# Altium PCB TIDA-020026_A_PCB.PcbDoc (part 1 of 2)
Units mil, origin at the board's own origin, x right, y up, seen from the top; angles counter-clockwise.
Board outline 2952.76 x 2952.76 mil, 2 copper layers (Top Layer, Bottom Layer), stack 62 mil thick; 75 components, 57 nets, 258 pads, 285 vias.
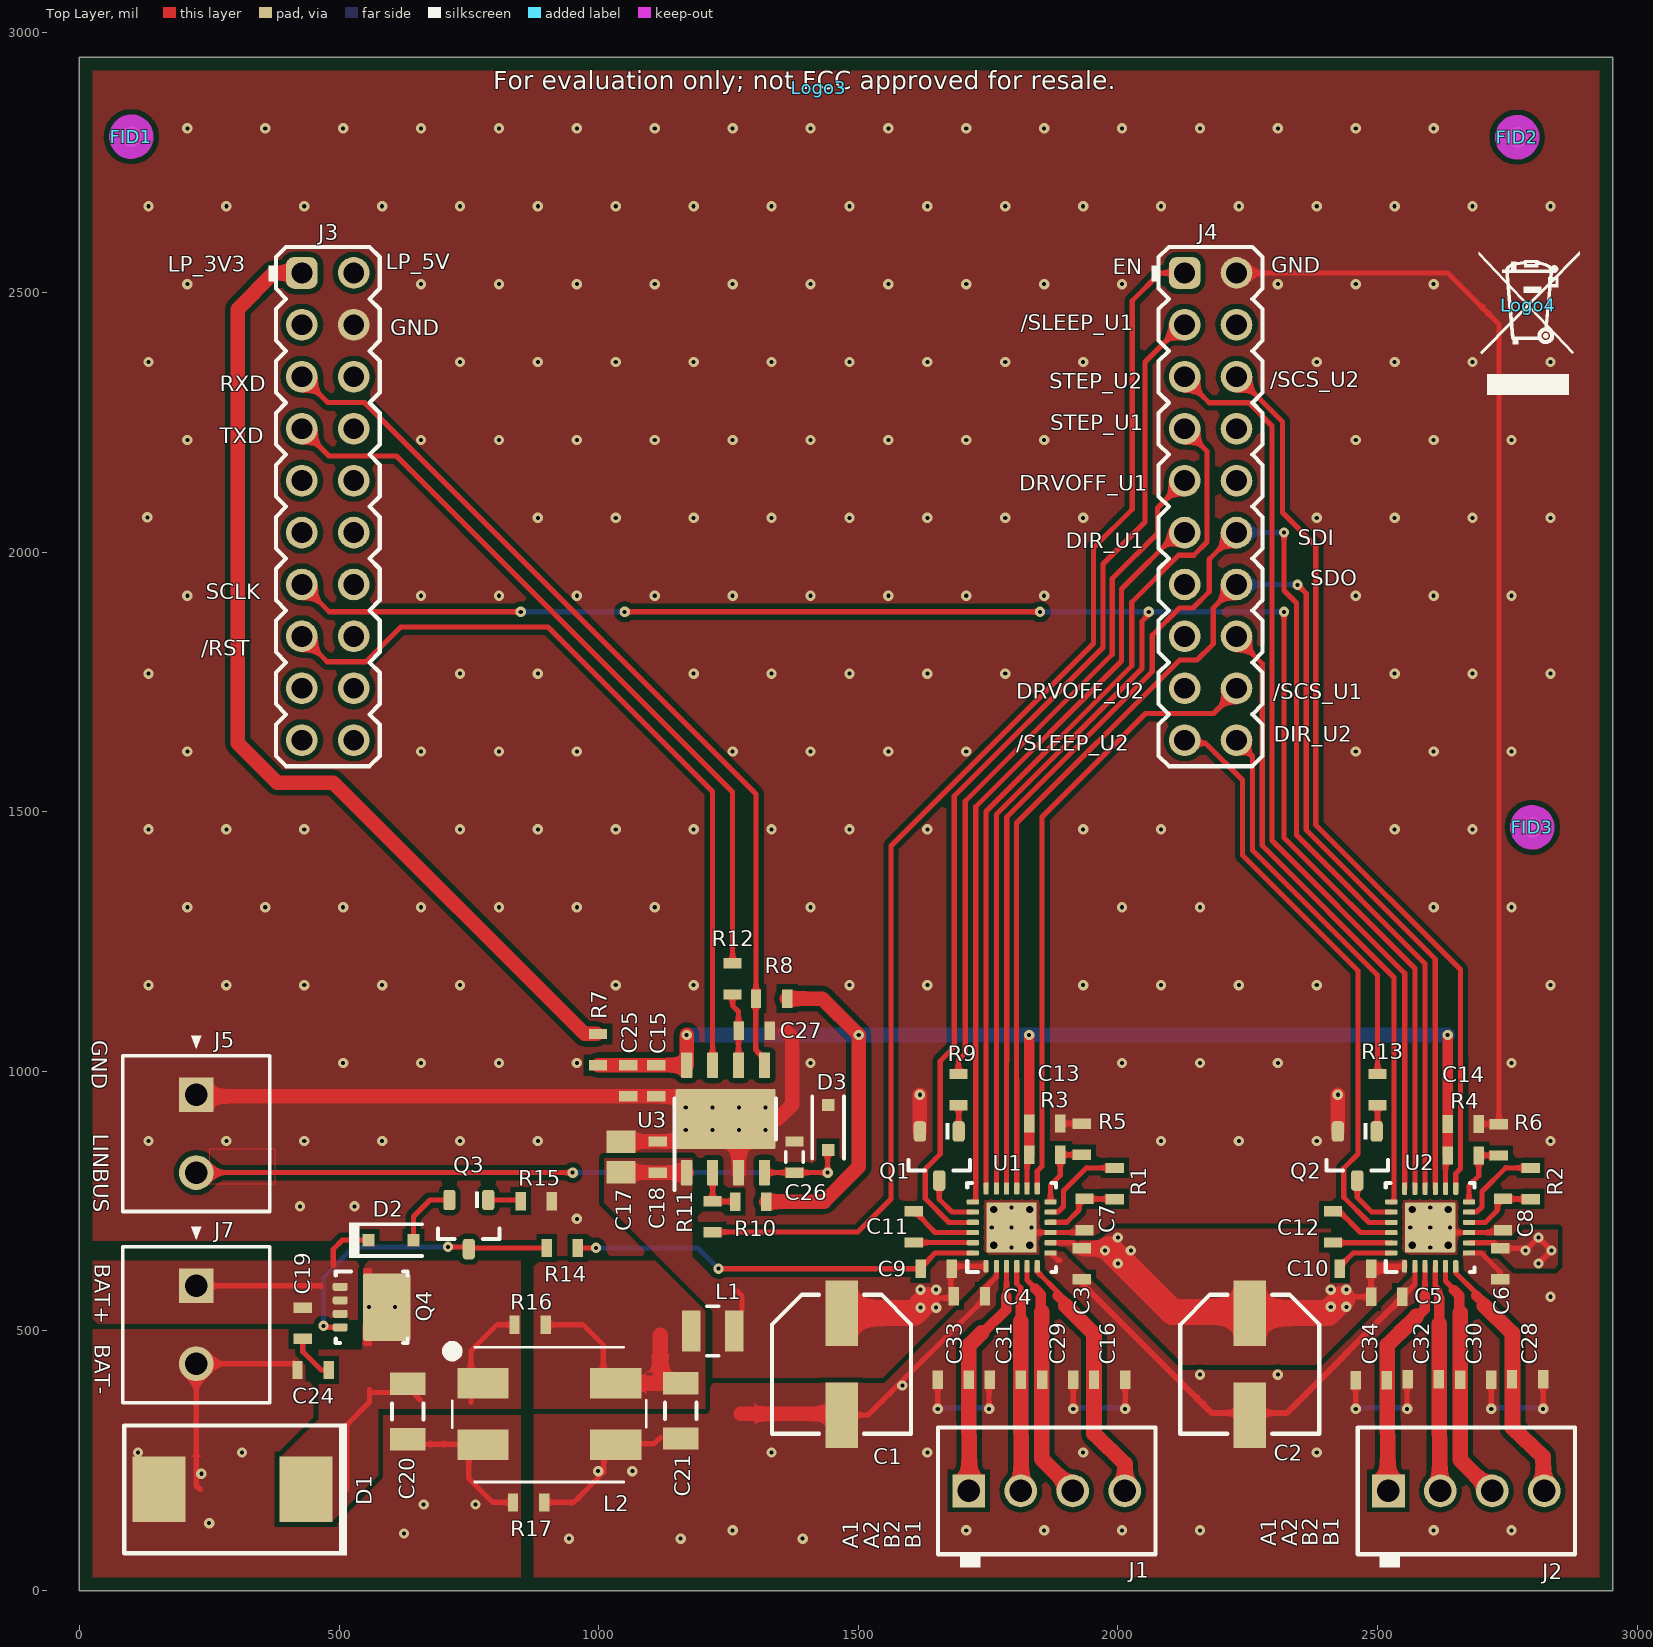
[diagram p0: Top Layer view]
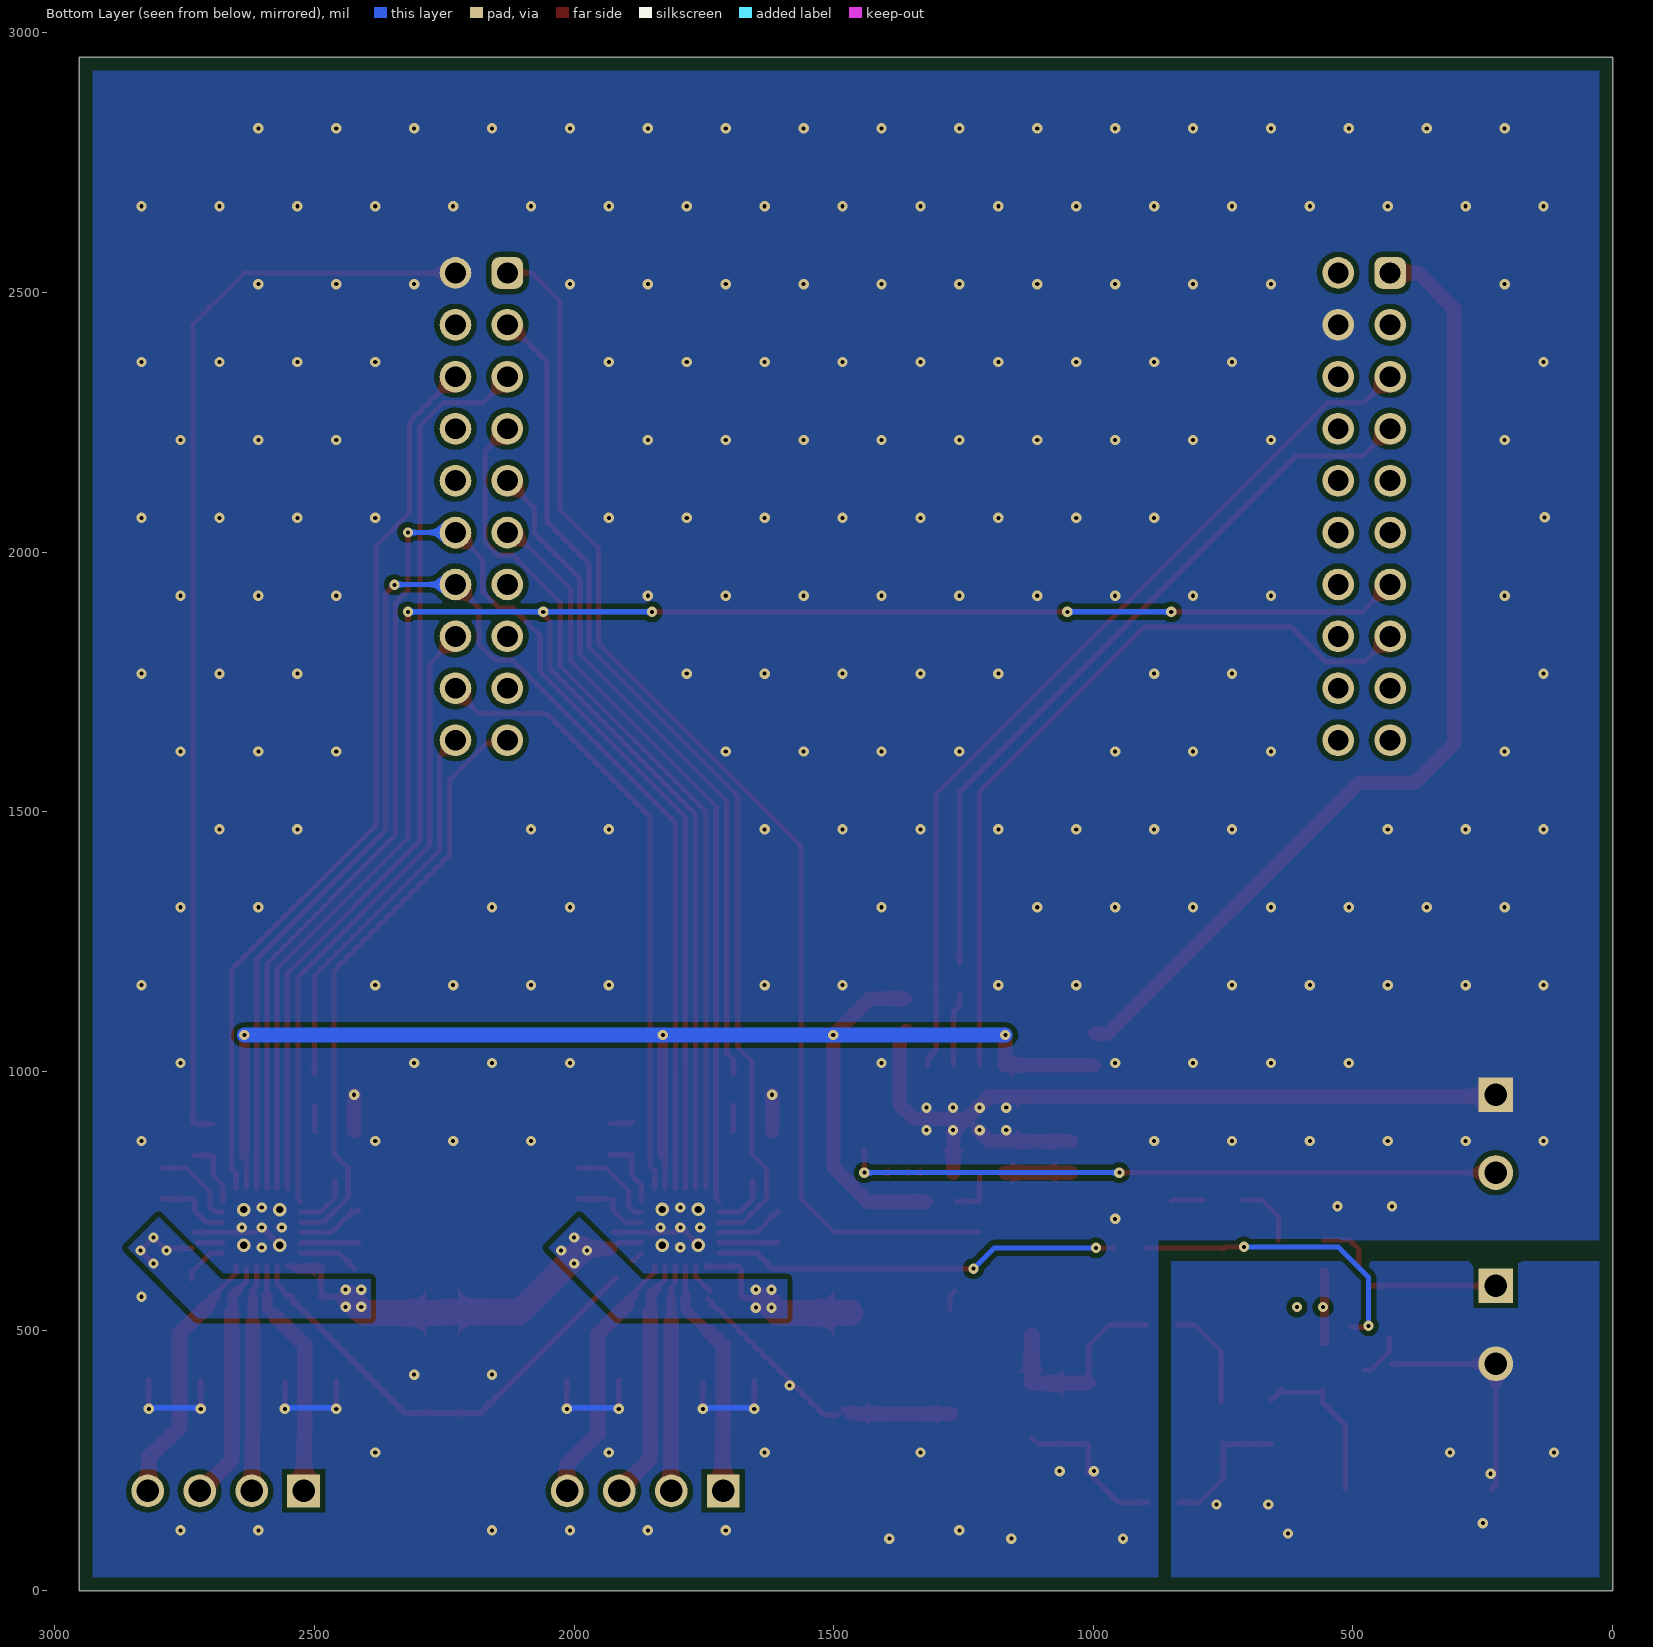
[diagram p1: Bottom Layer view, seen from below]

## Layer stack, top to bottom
Top Solder: solder mask 0.4, Solder Resist, Dk 3.5
Top Layer: signal copper 1.4
Dielectric1: core 59.2, FR-4, Dk 4.8
Bottom Layer: signal copper 1.4
Bottom Solder: solder mask 0.4, Solder Resist, Dk 3.5

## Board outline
0,0 2952.76,0 2952.76,2952.76 0,2952.76

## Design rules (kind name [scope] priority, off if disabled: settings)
AcuteAngle [All] p1: minimum=4.50000000000000E+0001 checktracksonly=FALSE
AssemblyTestPointUsage [All] p1: valid=2
BoardOutlineClearance BoardOutlineClearance_MountingHoles [OnCopper and InComponentClass('Mounting Holes')] p1: gap=39.37 ignorepadtopadclearanceinfootprint=FALSE
BoardOutlineClearance BoardOutlineClearance_Poly [OnCopper and IsPoly] p2: gap=25 ignorepadtopadclearanceinfootprint=FALSE
BoardOutlineClearance [OnCopper and Not InComponentClass('Logo') and not InComponentClass('FiducialMark') and not InRegion(1000,500,4000,800) and not InPoly] p3: gap=75 ignorepadtopadclearanceinfootprint=FALSE
Clearance Clearance_Keepouts [((IsTrack Or IsArc) And Not InPoly) And IsFree and IsKeepOut vs ((IsTrack Or IsArc) And Not InPoly) And IsFree and IsKeepOut] p1: gap=0 ignorepadtopadclearanceinfootprint=FALSE
Clearance Clearance_Poly [InPolygon] p2: gap=10 ignorepadtopadclearanceinfootprint=TRUE
Clearance Clearance_FiducialMark [IsKeepOut and InComponentClass('FiducialMark') vs IsPad and InComponentClass('FiducialMark')] p3: gap=0 ignorepadtopadclearanceinfootprint=FALSE
Clearance [All] p4: gap=7.87 ignorepadtopadclearanceinfootprint=TRUE
ComponentClearance ComponentClearance_MountingHoles_FiducialMarks [InComponentClass('Mounting Holes') vs InComponentClass('FiducialMark')] p1: gap=50 collisioncheckmode=3 verticalgap=10 showdistances=FALSE
ComponentClearance ComponentClearance_Shunt [InComponentClass('Header') vs InComponentClass('Shunt')] p2: gap=0 collisioncheckmode=3 verticalgap=0 showdistances=FALSE
ComponentClearance ComponentClearance_Logo [InComponentClass('Logo')] p3: gap=50 collisioncheckmode=3 verticalgap=10 showdistances=FALSE
ComponentClearance ComponentClearance_ScrewToNut [(HasFootprint('NY PMS 440 0025 PH')) vs (HasFootprint('Keystone_1902C'))] p4: gap=5 collisioncheckmode=3 verticalgap=10 showdistances=FALSE
ComponentClearance ComponentClearance_MountingHoles [InComponentClass('Mounting Holes')] p5: gap=250 collisioncheckmode=3 verticalgap=100000 showdistances=FALSE
ComponentClearance ComponentClearance_SmallPassives [HasFootprint('0201*') or HasFootprint('0402*') or HasFootprint('0508') or HasFootprint('0603*') or HasFootprint('0612') or HasFootprint('0805*') or HasFootprint('0815*') or HasFootprint('0830*') or HasFootprint('1206*') or HasFootprint('1210*') or HasFootprint('1808*') or HasFootprint('1812*') or HasFootprint('1825*') or HasFootprint('2010*') or HasFootprint('2220*') or HasFootprint('2225*') or HasFootprint('2512*') or HasFootprint('2728*') or HasFootprint('3518*') vs HasFootprint('0201*') or HasFootprint('0402*') or HasFootprint('0508') or HasFootprint('0603*') or HasFootprint('0612') or HasFootprint('0805*') or HasFootprint('0815*') or HasFootprint('0830*') or HasFootprint('1206*') or HasFootprint('1210*') or HasFootprint('1808*') or HasFootprint('1812*') or HasFootprint('1825*') or HasFootprint('2010*') or HasFootprint('2220*') or HasFootprint('2225*') or HasFootprint('2512*') or HasFootprint('2728*') or HasFootprint('3518*')] p6: gap=14.96 collisioncheckmode=3 verticalgap=10 showdistances=FALSE
ComponentClearance ComponentClearance_THtoSMT [IsThruComponent vs IsSMTComponent] p7: gap=40 collisioncheckmode=3 verticalgap=30 showdistances=FALSE
ComponentClearance ComponentClearance_THtoTH [IsThruComponent vs IsThruComponent] p8: gap=30 collisioncheckmode=3 verticalgap=30 showdistances=FALSE
ComponentClearance [All] p9: gap=15 collisioncheckmode=3 verticalgap=10 showdistances=FALSE
DiffPairsRouting [All] p1: maxlimit=100 minlimit=10 mostfreqgap=10 toplayer_minwidth=15 toplayer_maxwidth=15 toplayer_prefwidth=15 bottomlayer_minwidth=15 bottomlayer_maxwidth=15 bottomlayer_prefwidth=15 maxuncoupledlength=1000
FabricationTestPointUsage TestPointUsage [All] p1: valid=2 allowmultiple=FALSE
FabricationTestpoint Testpoint [All] p1: side=3 testpointundercomponent=TRUE minsize=40 maxsize=100 preferedsize=60 minholesize=0 maxholesize=40 preferedholesize=32 testpointgrid=1 allowsidetop=TRUE allowsidebottom=TRUE usegrid=TRUE gridtolerance=0.01
FanoutControl Fanout_LCC [IsLCC] p1: bgadir=Out bgaviamode=Centered fanoutstyle=Auto fanoutdirection=Alternating viagrid=1 // Fanout_LCC (Default Rule)
FanoutControl Fanout_BGA [IsBGA] p2: bgadir=Out bgaviamode=Centered fanoutstyle=Auto fanoutdirection=Alternating viagrid=1 // Fanout_BGA (Default Rule)
FanoutControl Fanout_Default [All] p4: bgadir=Out bgaviamode=Centered fanoutstyle=Auto fanoutdirection=Alternating viagrid=1 // Fanout_Default (Default Rule)
FanoutControl Fanout_Small [(CompPinCount < 5)] p5: bgadir=Out bgaviamode=Centered fanoutstyle=Auto fanoutdirection=OutThenIn viagrid=1 // Fanout_Small (Default Rule)
HoleSize [All] p1: absolutevalues=TRUE maxlimit=251 minlimit=7.87 maxpercent=80.000 minpercent=20.000
MinimumAnnularRing MinimumAnnularRing_ThermalPadVias [IsVia and InAnyComponent] p1: minimumring=5.91
MinimumAnnularRing [All] p2: minimumring=5
MinimumSolderMaskSliver MinimumSolderMaskSliver_Logo [InComponentClass('Logo') vs InComponentClass('Logo')] p1: minsoldermaskwidth=0.7
MinimumSolderMaskSliver [All] p2: minsoldermaskwidth=3.94
PlaneConnect [All] p1: planeconnectstyle=Direct reliefexpansion=10 reliefentries=4 reliefconductorwidth=10 reliefairgap=10
PolygonConnect [All] p1: connectstyle=Direct reliefconductorwidth=10 reliefentries=4 polygonreliefangle="90 Angle" airgapwidth=10
RoutingVias ThermalPadVias [IsVia and InAnyComponent] p1: holewidth=7.87 width=19.68 viastyle="Through Hole" minholewidth=7.87 minwidth=19.68 maxholewidth=12.99 maxwidth=23.62
RoutingVias [All] p2: holewidth=16 width=34 viastyle="Through Hole" minholewidth=7.87 minwidth=18 maxholewidth=40 maxwidth=65
SilkToBoardRegionClearance [Not ((IsComment or IsDesignator) And (Hide <> 'False')) and not InRegion(1000,500,4000,800)] p1:
SilkToSilkClearance SilkToSilkClearance_Pb-FreeLogo [(HasFootprint('Pb-Free_Overlay_Medium') OR HasFootprint('Pb-Free_Overlay_Small')) vs (HasFootprint('Pb-Free_Overlay_Medium') OR HasFootprint('Pb-Free_Overlay_Small'))] p1: silktosilkclearance=0
SilkToSilkClearance [All] p2: silktosilkclearance=3.94
SilkToSolderMaskClearance SilkToComponentPadClearance [(IsPad or IsFill or IsRegion) and InAnycomponent] p1: minsilkscreentomaskgap=3 clearancetoexposedcopper=TRUE
SilkToSolderMaskClearance "Silk to Solder Mask Opening" [All] p2: minsilkscreentomaskgap=3.94 clearancetoexposedcopper=FALSE
SolderMaskExpansion [All] p1: expansion=1.97
UnRoutedNet [All] p1: checkbadconnections=TRUE
Width [All] p1: maxlimit=100 minlimit=6 preferedwidth=10 checkconnectedcopper=TRUE
14 further rules are at their usual default settings.

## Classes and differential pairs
component class TIDA-Headlight-leveling_Hardware: !PCB FID1 FID2 FID3 Logo3 Logo4 ZZ2 ZZ3 ZZ4
component class TIDA-020026-A: C1 C2 C3 C4 C5 C6 C7 C8 C9 C10 C11 C12 C13 C14 C15 C16 C17 C18 C19 C20 C21 C24 C25 C26 C27 C28 C29 C30 C31 C32 C33 C34 D1 D2 D3 J1 J2 J3 J4 J5 J7 L1 L2 Q1 Q2 Q3 Q4 Q? R1 R2 R3 R4 R5 R6 R7 R8 R9 R10 R11 R12 R13 R14 R15 R16 R17 U1 U2 U3
component class Header: J3 J4
component class FiducialMark: FID1 FID2 FID3
component class AssemblyNote: ZZ2 ZZ3 ZZ4

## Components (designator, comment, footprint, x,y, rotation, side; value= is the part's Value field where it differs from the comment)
C1 "EEEFT1H470AP" Panasonic_D 1468,436 r270 top value=47uF
C2 "EEEFT1H470AP" Panasonic_D 2254,436 r270 top value=47uF
C3 "GCM188R71H103KA37D" 0603S 1930.47,629.34 r270 top value=0.01uF
C4 "GCM188R71H103KA37D" 0603S 1714,567 r0 top value=0.01uF
C5 "GCM188R71H103KA37D" 0603S 2517.62,565.82 r0 top value=0.01uF
C6 "GCM188R71H103KA37D" 0603S 2736.47,629.34 r270 top value=0.01uF
C7 "GCM188R71C474KA55D" 0603S 1935.47,724.34 r270 top value=0.47uF
C8 "GCM188R71C474KA55D" 0603S 2741.47,724.34 r270 top value=0.47uF
C9 "GRM188R71E224KA88D" 0603S 1650,619.88 r180 top value=0.22uF
C10 "GRM188R71E224KA88D" 0603S 2457.56,619.88 r180 top value=0.22uF
C11 "CGA3E2X7R2A223K080AA" 0603S 1607,700.5 r270 top value=0.022uF
C12 "CGA3E2X7R2A223K080AA" 0603S 2414,700.5 r270 top value=0.022uF
C13 "GCM188R71C104KA37J" 0603S 1859,899.34 r0 top value=0.1uF
C14 "GCM188R71C104KA37J" 0603S 2665,898.67 r0 top value=0.1uF
C15 "GCM188R71C104KA37J" 0603S 1111,982 r270 top value=0.1uF
C16 "C0603C102J5RACAUTO" 0603S 1984,406 r180 top value=1000pF
C17 "UMK212BB7225KG-T" 0805L 1043,835 r90 top value=2.2uF
C18 "C0603C104K5RACAUTO" 0603S 1114,835 r90 top value=0.1uF
C19 "CGA3E3X7S2A473K080AB" 0603S 430,515 r270 top value=0.047uF
C20 "GRT31CR61H106KE01L" 1206_180L 632.49,345 r270 top value=10uF
C21 "GRT31CR61H106KE01L" 1206_180L 1158,346.1 r270 top value=10uF
C24 "CGA3E3X7S2A473K080AB" 0603S 450,425 r180 top value=0.047uF
C25 "GRT188C81A106ME13D" 0603S 1057,982 r270 top value=10uF
C26 "CGA3E2C0G1H221J080AA" 0603S 1377,835 r90 top value=220pF
C27 "CGA3E2NP01H101J080AA" 0603S 1299.52,1078.35 r0 top value=100pF
C28 "C0603C102J5RACAUTO" 0603S 2789,407 r180 top value=1000pF
C29 "C0603C102J5RACAUTO" 0603S 1884,406 r180 top value=1000pF
C30 "C0603C102J5RACAUTO" 0603S 2689,406 r180 top value=1000pF
C31 "C0603C102J5RACAUTO" 0603S 1783,406 r0 top value=1000pF
C32 "C0603C102J5RACAUTO" 0603S 2588,407 r0 top value=1000pF
C33 "C0603C102J5RACAUTO" 0603S 1683,406 r0 top value=1000pF
C34 "C0603C102J5RACAUTO" 0603S 2488,405 r0 top value=1000pF
D1 "TPSMD26A" SMC_265 295,195 r180 top value=26V
D2 "1N4148WS-7-F" SOD-323 600,675 r0 top value=75V
D3 "PESD1LIN,115" SOD-323-Bi 1442,892 r270 top value=15V
FID1 "Fiducial" Fiducial10-20 100,2800 r90 top
FID2 "Fiducial" Fiducial10-20 2769,2799 r90 top
FID3 "Fiducial" Fiducial10-20 2798,1470 r90 top
J1 "1725672" Phoenix_1725672 1863,192 r0 top
J2 "1725672" Phoenix_1725672 2671,192 r0 top
J3 "PEC10DAAN" SULLINS_PEC10DAAN 478.47,2087.65 r0 top
J4 "PEC10DAAN" SULLINS_PEC10DAAN 2178.47,2087.65 r0 top
J5 "1727010" PhoenixConact_1727010 225,880 r270 top
J7 "1727010" PhoenixConact_1727010 225,512 r270 top
L1 "DFE252012P-2R2M=P2" DFE252012P 1220,500 r0 top value=2.2uH
L2 "ACM70V-701-2PL-TL00" IND_TDK_ACM7060 905,340 r0 top
Logo3 "FCC disclaimer" FCC_disclaimer 1424,2894 r0 top
Logo4 "WEEE logo" WEEE_Minimum 2790,2475 r0 top
Q1 "MMBT6429LT1G" SOT-23 1656,837 r270 top value="45 V"
Q2 "MMBT6429LT1G" SOT-23 2461,837 r270 top value="45 V"
Q3 "MMBTA05LT1G" SOT-23 750,705 r270 top value="60 V"
Q4 "SQ7414AEN-T1-GE3" PowerPAK_1212-8 562.68,546.02 r0 top value=60V
R1 "CRCW060310K0FKEA" 0603S 1994,784 r90 top value=10.0k
R2 "CRCW060310K0FKEA" 0603S 2795,784 r90 top value=10.0k
R3 "CRCW060310K0FKEA" 0603S 1859,839.34 r180 top value=10.0k
R4 "CRCW060310K0FKEA" 0603S 2665,838.02 r180 top value=10.0k
R5 "CRCW060310K0FKEA" 0603S 1930.47,869.34 r270 top value=10.0k
R6 "CRCW060310K0FKEA" 0603S 2733.42,868.02 r270 top value=10.0k
R7 "CRCW08050000Z0EA" 0603S 999,1042 r90 top value=0
R8 "CRCW060310K0FKEA" 0603S 1333.04,1140 r0 top value=10.0k
R9 "CRCW06031K00FKEA" 0603S 1693,965 r270 top value=1.00k
R10 "CRCW060310K0FKEA" 0603S 1293,749 r0 top value=10.0k
R11 "CRCW060310K0FKEA" 0603S 1219.52,720 r270 top value=10.0k
R12 "CRCW06031K00FKEA" 0603S 1258,1178 r90 top value=1.00k
R13 "CRCW06031K00FKEA" 0603S 2500,965 r270 top value=1.00k
R14 "CRCW060310K0FKEA" 0603S 930,660 r0 top value=10.0k
R15 "CRCW060310K0FKEA" 0603S 880,750 r180 top value=10.0k
R16 "CRCW08050000Z0EA" 0603S 868,512 r0 top value=0
R17 "CRCW08050000Z0EA" 0603S 865,170 r0 top value=0
U1 "DRV8889QWRGERQ1" RGE0024J 1795.47,699.47 r90 top
U2 "DRV8889QWRGERQ1" RGE0024J 2601.47,699.34 r90 top
U3 "TLIN1028DDA" DDA0008G_L 1244.52,908.35 r90 top
ZZ2 "These assemblies are ESD sensitive, ESD precautions shall be observed." AssemblyNote 156,3325 r0 top
ZZ3 "These assemblies must be clean and free from flux and all contaminants. Use of no clean flux is not acceptable." AssemblyNote 156,3178 r0 top
ZZ4 "These assemblies must comply with workmanship standards IPC-A-610 Class 2, unless otherwise specified." AssemblyNote 150.7,3045 r0 top

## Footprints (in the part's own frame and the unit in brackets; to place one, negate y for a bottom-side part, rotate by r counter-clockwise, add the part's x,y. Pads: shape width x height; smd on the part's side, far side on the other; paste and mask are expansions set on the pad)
0603S [mil]
  rect 20x35 smd: 1(-30,0) 2(30,0)
  body extent -34,-19 34,19, height 39
0805L [mm] "0805 from SM-752 data"
  rect 1.1x1.4 smd: 1(-0.75,0) 2(0.75,0)
  body extent -1.1,-0.72 1.1,0.72, height 1.45
1206_180L [mm] "1206_180"
  rect 1.1x1.75 smd: 1(-1.35,0) 2(1.35,0)
  silkscreen extent -0.4,-0.77 0.4,0.77, body extent -1.75,-0.95 1.75,0.95, height 1.8
AssemblyNote [mil] "Assembly Note"
DDA0008G_L [mm] "SOIC, 8-Leads, Body 4.9x3.9mm, Pitch 1.27mm, Exposed Pad, IPC High Density"
  rrect18% 1.25x0.55 smd: 1(-2.625,1.905) 2(-2.625,0.635) 3(-2.625,-0.635) 4(-2.625,-1.905) 5(2.625,-1.905) 6(2.625,-0.635) 7(2.625,0.635) 8(2.625,1.905)
  rrect7% 2.95x4.9 smd paste-1.5 mask-1.5: 9(0,0)
  rrect4% 2.29x3.1 on Top Paste: 9(0,0)
  rrect4% 2.29x3.1 on Top Solder: 9(0,0)
  silkscreen extent -3.47,-2.47 1,2.5, body extent -2.98,-2.45 2.98,2.45, height 1.55
DFE252012P [mm] "TOKO, Pad sizes increased as per request"
  rect 0.9x2 smd: 1(-1.05,0) 2(1.05,0)
  silkscreen extent -0.3,-1.2 0.3,1.2, body extent -1.35,-1.1 1.35,1.1, height 1.2
FCC_disclaimer [mil]
Fiducial10-20 [mm]
  round 1 smd mask+0.5: 1(0,0)
  Top Layer keep-out circle w1.178: c0,0 r0.5
IND_TDK_ACM7060 [mm] "TDK Common Mode EMI Filter 7mmx6mm"
  rect 2.5x1.5 smd: 1(-3.25,1.5) 2(-3.25,-1.5) 3(3.25,-1.5) 4(3.25,1.5)
  silkscreen extent -5,-3.32 4.75,3.32, body extent -3.6,-3.12 3.6,3.07, height 3.55
Panasonic_D [mm] "SMD, 2-Leads, Dia 6.3mm"
  rect 3.2x1.6 smd: 1(-2.5,0) 2(2.5,0)
  silkscreen extent -3.4,-3.4 3.4,3.4, body extent -3.4,-3.4 3.4,3.4, height 6.11
Phoenix_1725672 [mm] "Terminal Block, 4x1, 2.54 mm, TH"
  rect 1.6x1.6 hole 1.1: 1(-3.81,0)
  round 1.6 hole 1.1: 2(-1.27,0) 3(1.27,0) 4(3.81,0)
  silkscreen extent -5.31,-3.75 5.31,3.1, body extent -5.31,-3.1 5.31,3.1, height 9.01
PhoenixConact_1727010 [mm]
  rect 1.7x1.7 hole 1.1: 1(-1.905,0)
  round 1.7 hole 1.1: 2(1.905,0)
  silkscreen extent -4.8,-3.6 3.81,3.6, body extent -3.81,-3.6 3.81,3.7, height 8.52
PowerPAK_1212-8 [mm] "Vishay PowerPAK 1212-8, Body 3.4x3.2mm (max), Pitch 0.65mm, IPC Medium Density"
  rrect50% 0.73x0.4 smd paste-0.05 mask-0.05: 1(-1.535,0.991) 2(-1.535,0.33) 3(-1.535,-0.33) 4(-1.535,-0.991)
  rrect50% 0.71x0.4 smd paste-0.05 mask-0.05: 5(1.545,-0.991) 6(1.545,-0.33) 7(1.545,0.33) 8(1.545,0.991)
  rrect30% 0.33x0.6 on Top Paste: 9(-0.195,-1.55) 9(-0.195,1.55)
  rrect30% 0.33x3.7 on Top Solder: 9(-0.195,0)
  rrect11% 1.3x0.94 on Top Paste: 9(0.39,-0.57) 9(0.39,0.57)
  rrect6% 1.6x2.28 on Top Solder: 9(0.54,0)
  rrect9% 2.31x3.3 smd paste-2 mask-2: 9(0.745,0)
  Top Layer region: -0.41,-1.8 -0.41,1.8 -0.402,1.838 -0.381,1.871 -0.348,1.892 -0.31,1.9 -0.31,1.9 -0.08,1.9 -0.042,1.892 -0.009,1.871 0.012,1.838 0.02,1.8 0.02,1.8 0.02,-1.8 0.012,-1.838 -0.009,-1.871 -0.042,-1.892 -0.08,-1.9 -0.08,-1.9 -0.31,-1.9 -0.348,-1.892 -0.381,-1.871 -0.402,-1.838 -0.41,-1.8
  silkscreen extent -1.75,-1.75 1.75,1.75, body extent -1.65,-1.66 1.65,1.64, height 1.08
RGE0024J [mm] "QFN, 24-Leads, Body 4x4mm, Pitch 0.5mm, Thermal Pad 2.45x2.45mm, TI Recommended"
  rrect40% 0.6x0.25 smd: 1(-1.9,1.25) 2(-1.9,0.75) 3(-1.9,0.25) 4(-1.9,-0.25) 5(-1.9,-0.75) 6(-1.9,-1.25) 13(1.9,-1.25) 14(1.9,-0.75) 15(1.9,-0.25) 16(1.9,0.25) 17(1.9,0.75) 18(1.9,1.25)
  rrect40% 0.25x0.6 smd: 7(-1.25,-1.9) 8(-0.75,-1.9) 9(-0.25,-1.9) 10(0.25,-1.9) 11(0.75,-1.9) 12(1.25,-1.9) 19(1.25,1.9) 20(0.75,1.9) 21(0.25,1.9) 22(-0.25,1.9) 23(-0.75,1.9) 24(-1.25,1.9)
  rrect9% 1.08x1.08 on Top Paste: 25(-0.64,-0.64) 25(-0.64,0.64) 25(0.64,-0.64) 25(0.64,0.64)
  rrect4% 2.45x2.45 smd paste-1.225: 25(0,0)
  silkscreen extent -2.17,-2.17 2.17,2.17, body extent -2,-2 2,2, height 1
SMC_265 [mm] "SMD, 2-Leads, Body 7.15x6.25mm"
  rect 2.6x3.2 smd: 1(-3.6,0) 2(3.6,0)
  silkscreen extent -5.6,-3.22 5.3,3.23, body extent -4.07,-3.13 4.07,3.13, height 2.65
SOD-323 [mm] "NXP recommended land pattern"
  rect 0.6x0.6 smd paste-0.05: 1(-1.1,0) 2(1.1,0)
  silkscreen extent -2.06,-0.86 1.53,0.86, body extent -1.3,-0.67 1.3,0.68, height 1.1
SOD-323-Bi [mm] "SOD323, 2-Leads, Body 1.9x1.45mm, No Polarity Mark"
  rect 0.6x0.6 smd paste-0.05: 1(-1.1,0) 2(1.1,0)
  silkscreen extent -1.53,-0.77 1.53,0.77, body extent -1.27,-0.65 1.27,0.65, height 1.02
SOT-23 [mm] "SOT23, 3-Leads, Body 2.9x1.3mm, Pitch 0.95mm, Lead Span 2.5mm, IPC Medium Density"
  rrect50% 1x0.6 smd: 1(-1.2,0.95) 2(-1.2,-0.95) 3(1.2,0)
  silkscreen extent -1.63,-1.5 0.7,1.5, body extent -1.16,-1.45 1.21,1.45, height 1
SULLINS_PEC10DAAN [mm] "SULLINS"
  rrect50% 1.55x1.55 hole 1.016: 1(-1.27,11.43)
  round 1.55 hole 1.016: 2(1.27,11.43) 3(-1.27,8.89) 4(1.27,8.89) 5(-1.27,6.35) 6(1.27,6.35) 7(-1.27,3.81) 8(1.27,3.81) 9(-1.27,1.27) 10(1.27,1.27) 11(-1.27,-1.27) 12(1.27,-1.27) 13(-1.27,-3.81) 14(1.27,-3.81) 15(-1.27,-6.35) 16(1.27,-6.35) 17(-1.27,-8.89) 18(1.27,-8.89) 19(-1.27,-11.43) 20(1.27,-11.43)
  silkscreen extent -2.9,-12.7 2.54,12.7, body extent -2.54,-12.7 2.54,12.7, height 8.38
WEEE_Minimum [mil] "WEEElie bin"
  silkscreen extent -95,-172 99,104

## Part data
C1 C2: library part CMP-0011204-2, "CAP, AL, 47 uF, 50 V, +/- 20%, 0.68 ohm, AEC-Q200 Grade 2, SMD", Cap_Case=6.3x5.8mm, Manufacturer=Panasonic, Supplier Part Number 1=PCE5023CT-ND, Tolerance_%=20%, Value1="0.68 ohm", Value2=50V, ValueDisplayed=47uF
C3 C4 C5 C6: library part CMP-0007143-4, "CAP, CERM, 0.01 uF, 50 V, +/- 10%, X7R, AEC-Q200 Grade 1, 0603", Cap_Case=0603, Manufacturer=MuRata, Supplier Part Number 1=490-4778-1-ND, TempCo=X7R, Tolerance_%=10%, Value1=Unknown, Value2=50V, ValueDisplayed=0.01uF
C7 C8: library part CMP-0007138-4, "CAP, CERM, 0.47 uF, 16 V, +/- 10%, X7R, AEC-Q200 Grade 1, 0603", Cap_Case=0603, Manufacturer=MuRata, Supplier Part Number 1=490-4775-1-ND, TempCo=X7R, Tolerance_%=10%, Value1=Unknown, Value2=16V, ValueDisplayed=0.47uF
C9 C10: library part CMP-0007415-4, "CAP, CERM, 0.22 uF, 25 V, +/- 10%, X7R, 0603", Cap_Case=0603, Manufacturer=MuRata, Supplier Part Number 1=490-3290-1-ND, TempCo=X7R, Tolerance_%=10%, Value1=Unknown, Value2=25V, ValueDisplayed=0.22uF
C11 C12: library part CMP-0007086-4, "CAP, CERM, 0.022 uF, 100 V, +/- 10%, X7R, AEC-Q200 Grade 1, 0603", Cap_Case=0603, Manufacturer=TDK, Supplier Part Number 1=445-5814-1-ND, TempCo=X7R, Tolerance_%=10%, Value1="0.083542 ohm", Value2=100V, ValueDisplayed=0.022uF
C13 C14 C15: library part CMP-0007135-4, "CAP, CERM, 0.1 uF, 16 V, +/- 10%, X7R, AEC-Q200 Grade 1, 0603", Cap_Case=0603, Manufacturer=MuRata, Supplier Part Number 1=490-8015-1-ND, TempCo=X7R, Tolerance_%=10%, Value1=Unknown, Value2=16V, ValueDisplayed=0.1uF
C16 C28 C29 C30 C31 C32 C33 C34: library part CMP-0006844-4, "CAP, CERM, 1000 pF, 50 V, +/- 5%, X7R, AEC-Q200 Grade 1, 0603", Cap_Case=0603, Manufacturer=Kemet, Supplier Part Number 1=399-12989-1-ND, TempCo=X7R, Tolerance_%=5%, Value1=Unknown, Value2=50V, ValueDisplayed=1000pF
C17: library part CMP-0008425-2, "CAP, CERM, 2.2 uF, 50 V, +/- 10%, X7R, 0805", Cap_Case=0805, Manufacturer="Taiyo Yuden", Supplier Part Number 1=587-3169-1-ND, TempCo=X7R, Tolerance_%=10%, Value1=Unknown, Value2=50V, ValueDisplayed=2.2uF
C18: library part CMP-0079602-1, "CAP, CERM, 0.1 µF, 50 V,+/- 10%, X7R, AEC-Q200 Grade 1, 0603", Cap_Case=0603, Manufacturer=Kemet, Supplier Part Number 1=399-6856-1-ND, TempCo=X7R, Tolerance_%=10%, Value2=50V, ValueDisplayed=0.1µF
C19 C24: library part CMP-0007101-4, "CAP, CERM, 0.047 uF, 100 V, +/- 10%, X7S, AEC-Q200 Grade 1, 0603", Cap_Case=0603, Manufacturer=TDK, Supplier Part Number 1=445-6936-1-ND, TempCo=X7S, Tolerance_%=10%, Value1="0.089796 ohm", Value2=100V, ValueDisplayed=0.047uF
C20 C21: library part CMP-0009015-2, "CAP, CERM, 10 uF, 50 V, +/- 10%, X5R, AEC-Q200 Grade 1, 1206", Cap_Case=1206, Manufacturer=MuRata, Supplier Part Number 1=490-12456-1-ND, TempCo=X5R, Tolerance_%=10%, Value1=Unknown, Value2=50V, ValueDisplayed=10uF
C25: library part CMP-0007500-4, "CAP, CERM, 10 uF, 10 V, +/- 20%, X6S, AEC-Q200 Grade 2, 0603", Cap_Case=0603, Manufacturer=MuRata, Supplier Part Number 1=490-12283-1-ND, TempCo=X6S, Tolerance_%=20%, Value1=Unknown, Value2=10V, ValueDisplayed=10uF
C26: library part CMP-0007072-1, "CAP, CERM, 220 pF, 20 V, +/- 5%, C0G/NP0, AEC-Q200 Grade 1, 0603", Cap_Case=0603, Manufacturer=TDK, Supplier Part Number 1=445-5644-1-ND, TempCo=C0G/NP0, Tolerance_%=5%, Value1=Unknown, Value2=20V, ValueDisplayed=220pF
C27: library part CMP-0007075-4, "CAP, CERM, 100 pF, 50 V, +/- 5%, C0G/NP0, AEC-Q200 Grade 0, 0603", Cap_Case=0603, Manufacturer=TDK, Supplier Part Number 1=445-12386-1-ND, TempCo=C0G/NP0, Tolerance_%=5%, Value1=Unknown, Value2=50V, ValueDisplayed=100pF
D1: library part CMP-0005729-4, "Diode, TVS, Uni, 26 V, 42.1 Vc, AEC-Q101, SMC", Manufacturer=Littelfuse, Value1=3000W
D2: library part CMP-0079597-2, "Diode, Switching, 75 V, 0.15 A, AEC-Q101, SOD-323", Manufacturer="Diodes Inc.", Value1=0.15A, Value2=1.25V
D3: library part CMP-0005821-3, "Diode, TVS, Bi, 15 V, SOD-323", Manufacturer="NXP Semiconductor", Value1=160W
FID1 FID2 FID3: library part CMP-0077181-1, "Fiducial mark.  There is nothing to buy or mount.", Manufacturer=N/A
J1 J2: library part CMP-0055518-1, "Terminal Block, 4x1, 2.54 mm, Green, TH", Color=Green, Current_A=6A, Manufacturer="Phoenix Contact", Supplier Part Number 1=277-1275-ND, Voltage_V=125V
J3 J4: library part CMP-0054623-2, "Header, 2.54mm, 10x2, Tin, TH", Color=Black, Current_A=3A, Manufacturer="Sullins Connector Solutions", Supplier Part Number 1=S2012E-10-ND
J5 J7: library part CMP-0055472-1, "Conn Term Block, 2POS, 3.81mm, TH", Manufacturer="Phoenix Contact", Supplier Part Number 1=277-1947-ND
L1: library part CMP-0058936-2, "Inductor, Shielded, Metal Composite, 2.2 µH, 2.2 A, 0.084 ohm, SMD", Manufacturer=MuRata, PartNumber=DFE252012P-2R2M{}P2, Value1="0.084 ohm", Value2=2.2A, ValueDisplayed=2.2uH
L2: library part CMP-0085405-1, "Coupled inductor, 0.015 ohm, AEC-Q200 Grade 1, SMD", Manufacturer=TDK
Logo3: library part CMP-0074847-1, "FCC_disclaimer"
Logo4: library part CMP-0074769-1
Q1 Q2: library part CMP-0078179-2, "Transistor, NPN, 45 V, 0.2 A, AEC-Q101, SOT-23", Manufacturer="ON Semiconductor", Value1="0.2 A", Value2=1250
Q3: library part CMP-0000488-2, "Transistor, NPN, 60 V, 0.5 A, AEC-Q101, SOT-23", Manufacturer="ON Semiconductor", Supplier Part Number 1=MMBTA05LT1GOSCT-ND, Value1="0.5 A"
Q4: library part CMP-0000873-2, "MOSFET, N-CH, 60 V, 16 A, AEC-Q101, PowerPAK 1212", Alternate Manufacturer=None, Manufacturer=Vishay-Siliconix, Supplier Part Number 1=SQ7414AEN-T1-GE3-ND, Value1=0.03, Value2="16 nC"
R1 R2 R3 R4 R5 R6 R8 R10 R11 R14 R15: library part CMP-0021998-4, "RES, 10.0 k, 1%, 0.1 W, AEC-Q200 Grade 0, 0603", Manufacturer=Vishay-Dale, Power_W=100mW, Supplier Part Number 1=541-10.0KHCT-ND, TempCo="100 ppm/C", Tolerance_%=1%, Value2=0.1W, Value_Code=10k0, ValueDisplayed=10.0k
R7 R16 R17: library part CMP-0025697-4, "RES, 0, 5%, 0.1 W, AEC-Q200 Grade 0, 0603", Manufacturer=Vishay-Dale, PartNumber=CRCW06030000Z0EA, Power_W=100mW, Supplier Part Number 1=541-0.0GCT-ND, TempCo="200 ppm/C", Tolerance_%=5%, Value2=0.1W, Value_Code=0000, ValueDisplayed=0
R9 R12 R13: library part CMP-0022109-5, "RES, 1.00 k, 1%, 0.1 W, AEC-Q200 Grade 0, 0603", Manufacturer=Vishay-Dale, Power_W=100mW, Supplier Part Number 1=541-1.00KHCT-ND, TempCo="100 ppm/C", Tolerance_%=1%, Value2=0.1W, Value_Code=1k00, ValueDisplayed=1.00k
U1 U2: library part CMP-0084889-1, "Automotive Stepper Driver With Integrated Current Sense, 1/32 Microstepping, and Stall Detection, RGE0024J (VQFN-24)", Alternate Manufacturer="Texas Instruments", Operating Temperature Range="-40 to 125 C", Rating=Automotive
U3: library part CMP-0074642-4, "Automotive Local Interconnect Network Transceiver, DDA0008G (SOIC-8)", Alternate Manufacturer="Texas Instruments"
ZZ2: library part CMP-0077236-1
ZZ3: library part CMP-0077237-1
ZZ4: library part CMP-0077238-1

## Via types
v1: diameter 19.87, hole 7.87, Top Layer to Bottom Layer, tented both sides, 257 vias
v2: diameter 19.68, hole 7.87, Top Layer to Bottom Layer, 16 vias
v3: diameter 26, hole 14, Top Layer to Bottom Layer, 8 vias
v4: diameter 19.68, hole 7.87, Top Layer to Bottom Layer, tented both sides, 4 vias

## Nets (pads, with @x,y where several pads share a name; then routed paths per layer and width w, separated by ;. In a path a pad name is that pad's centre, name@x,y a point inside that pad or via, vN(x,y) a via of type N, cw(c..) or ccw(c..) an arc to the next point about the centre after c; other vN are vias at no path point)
/FAULT_U1: R1.2 U1.11 | length 177
  Top Layer w10: U1.11@1870.28,728.87 1884.38,728.87 1894.96,739.46 1894.96,769.91 1939.4,814.34 R1.2@1994,814
/FAULT_U2: R2.2 U2.11 | length 171.5
  Top Layer w10: U2.11@2676.28,728.87 2690.91,728.87 2700.96,738.92 2700.96,768.38 2746.99,814.41 R2.2@2795,814 ; R2.2@2791.41,814.41 R2.2@2791.47,814.34
/RST: J3.15 U3.7 | length 1497.8
  Top Layer w10: J3.15@428.47,1837.65 477.36,1788.77 551.77,1788.77 619,1856 902.56,1856 1219.52,1539.04 U3.7@1219.52,1011.7
/SCS_U1: J4.18 U1.13 | length 1197.2
  Top Layer w10: U1.13@1844.68,774.15 1844.68,807.85 1854,817.17 1854,1490 2053,1689 2184,1689 J4.18@2230,1735
/SCS_U2: J4.6 U2.13 | length 1747
  Top Layer w10: J4.6@2229,2339 2317,2251 2317,2076 2381,2012 2381,1474.57 2659.56,1196 2659.97,847 2659.97,812.82 2650.68,803.54 U2.13@2650.68,774.15
/SLEEP_U1: J4.3 U1.21 | length 2004.7
  Top Layer w10: U1.21@1720.67,709.19 1675,709.19 1629,755.19 1629,812 1658,841 1658,1019.81 1685,1046.81 1685,1530 1971.13,1816.13 1971.13,1977.13 2052,2058 2052,2366 J4.3@2128,2442 ; J4.3@2128,2437.65 J4.3@2128.47,2437.65
/SLEEP_U2: J4.19 U2.21 | length 1161.2
  Top Layer w10: J4.19@2127,1632 2169,1632 2240,1561 2240,1416.27 2462.56,1193.71 2462.56,841 2435,813.44 2435,757.55 2483.36,709.19 U2.21@2526.67,709.19
AOUT1_U1: C33.2 J1.1 U1.3 | length 454.2
  Top Layer w10: 1785,567 U1.3@1785.63,624.54
  Top Layer w20: 1743.5,500.09 1785,541 1785,567
  Top Layer w30: J1.1@1714,195 C33.2@1713,406 1713,472 1738,497
AOUT1_U2: C34.2 J2.1 U2.3 | length 456
  Top Layer w10: 2591,568 U2.3@2591.63,625.54
  Top Layer w20: 2579,530 2591,542 2591,568
  Top Layer w30: J2.1@2520,196 2519,407 2519,473 2544,498 ; 2544.22,497.78 2574.99,528.01
AOUT2_U1: C31.2 J1.2 U1.4 | length 427.7
  Top Layer w10: U1.4@1805.31,624.54 1805.31,590.84 1812.94,583.22 1812.94,563
  Top Layer w20: 1812.94,563 1813,522.31
  Top Layer w30: 1813,518.31 C31.2@1813,406 J1.2@1814,196
AOUT2_U2: C32.2 J2.2 U2.4 | length 427.7
  Top Layer w10: U2.4@2611.31,624.54 2611.31,587.69 2618.94,580.06 2618.94,563
  Top Layer w20: 2618.94,563 2619,522.31
  Top Layer w30: 2619,514.31 2619,402 J2.2@2620,192
BAT+: C19.1 D2.1 J7.1 Q4.1 Q4.2 Q4.3 | length 346.3
  Top Layer w10: J7.1@225,587 464,587 465,586 ; 488.78,626.72 488.78,657.36 506.42,675 D2.1@556.69,675
BAT-: C20.2 C24.2 D1.2 J7.2 L2.2 R17.1 | length 711.7
  Top Layer w10: 225,200.27 225.27,200 ; 233.27,195 225,203.27 J7.2@225,437 C24.2@425,437 ; C20.2@657,282 L2.2@750,282 ; L2.2@752,284 L2.2@750,282 ; R17.1@835,170 796,170 750,216 L2.2@750,282
  other v1: 625,110 250,130 663,166 763,166 235,225 113,266 313,266
BOUT1_U1: C16.2 J1.4 U1.6 | length 491.8
  Top Layer w10: U1.6@1844.68,624.54 1844.68,614 1884.5,574.19 1884.5,567.85
  Top Layer w20: 1884.5,567.85 1899.19,553.16 1899.19,549
  Top Layer w30: 1899.19,549 1954,494.25 C16.2@1954,406 C16.2@1954,405 ; C16.2@1954,403 1954,302.42 2013.64,243.77 J1.4@2014,201
BOUT1_U2: C28.2 J2.4 U2.6 | length 485.2
  Top Layer w10: U2.6@2650.68,624.54 2650.68,611.81 2690.5,572 2690.5,567.85
  Top Layer w20: 2690.5,567.85 2705.19,553.16
  Top Layer w30: 2705.19,549 2760,495.25 C28.2@2760,406 ; C28.2@2760,404 2760,313.55 2818.62,257.86 J2.4@2820,204
BOUT2_U1: C29.2 J1.3 U1.5 | length 459
  Top Layer w10: U1.5@1825,624.54 1825,598 1842,581
  Top Layer w20: 1840.87,581 1841,581 1851.62,570.38 1851.62,546.38
  Top Layer w30: 1853,537 1853,254 J1.3@1914,193
BOUT2_U2: C30.2 J2.3 U2.5 | length 458.9
  Top Layer w10: U2.5@2631,622.54 2631,596 2648,579
  Top Layer w20: 2647,579 2657.62,568.38 2657.62,544.38
  Top Layer w30: 2659,535 C30.2@2659,406 2659,252 J2.3@2720,191
CPH_U1: C11.2 U1.23 | length 114.9
  Top Layer w10: C11.2@1606.69,670.5 C11.2@1607.58,671.39 ; C11.2@1607,670.5 U1.23@1720.67,669.82
CPH_U2: C12.2 U2.23 | length 113
  Top Layer w10: C12.2@2414,670.5 2414.68,669.82 U2.23@2526.67,669.82
CPL_U1: C11.1 U1.22 | length 131.3
  Top Layer w10: C11.1@1607,730.5 1608.63,728.87 1610.66,728.87 1648,689.5 U1.22@1720.67,689.5
CPL_U2: C12.1 U2.22 | length 129.7
  Top Layer w10: C12.1@2414,730.5 2426.5,730.5 2467.5,689.5 U2.22@2526.67,689.5
DIR_U1: J4.11 U1.19 | length 1466
  Top Layer w10: U1.19@1720.67,748.56 1726.2,754.08 1726.2,1509.63 2007,1790.43 2007,1929 2118,2040 J4.11@2128,2040
DIR_U2: J4.16 U2.19 | length 1214.8
  Top Layer w10: J4.16@2230,1836 2229.96,1833.04 2278,1785 2278,1435 2532,1181 2532,753.89 U2.19@2526.67,748.56
DRVOFF_1: Q1.3 U1.20 | length 111.1
  Top Layer w10: Q1.3@1656,789.76 1656,753.6 1680.73,728.87 U1.20@1720.67,728.87
DRVOFF_2: Q2.3 U2.20 | length 110.2
  Top Layer w10: Q2.3@2461,789.76 2461,756.83 2488.96,728.87 U2.20@2526.67,728.87
DRVOFF_U1: J4.9 R9.1 | length 1324.1
  Top Layer w10: R9.1@1693,995 1693,1022 1706,1035 1706,1520.15 1989,1803.15 1989,1949 2076,2036 2076,2085 J4.9@2129,2138 ; J4.9@2128,2137.65 J4.9@2128.47,2137.65
DRVOFF_U2: J4.20 R13.1 | length 755.1
  Top Layer w10: J4.20@2228.47,1637.65 2259.25,1606.87 2259.25,1425.75 2500,1185 R13.1@2500,995
DVDD_U1: C7.1 R1.1 U1.10 | length 144.9
  Top Layer w10: U1.10@1870.28,709.31 1901.63,709.31 1925.12,732.8 C7.1@1925.12,754.47 ; C7.1@1935.47,754.34 1993.66,754.34 R1.1@1994,754
DVDD_U2: C8.1 R2.1 U2.10 | length 151.5
  Top Layer w10: U2.10@2676.28,709.19 2707.63,709.19 2731.12,732.67 2731.12,754.34 C8.1@2741.47,754.34 R2.1@2795,754 ; R2.1@2791.69,755.41 R2.1@2792.69,754.41
EN: J4.1 R11.2 | length 2415.1
  Top Layer w10: R11.2@1219.52,690.47 1499.13,690.47 1563,754.34 1563,1434 1953.25,1824.25 1953.25,2008.25 2027.6,2082.6 2027.6,2484.02 2081.23,2537.65 J4.1@2128.47,2537.65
